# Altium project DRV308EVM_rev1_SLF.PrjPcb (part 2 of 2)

## Sheet DRV7308EVM_rev1_POWER_AND_CONNECTORS_SLF.SchDoc
size 431 x 279 mm; Date: Not shown in title block; ApprovedBy: Not shown in title block; CheckedBy: Not shown in title block; Author: Not shown in title block; CompanyName: Not shown in title block; DrawnBy: Anthony Lodi; Engineer: Not shown in title block; Organization: Not shown in title block; Address1: Not shown in title block; Address2: Not shown in title block; Address3: Not shown in title block; Address4: Not shown in title block; DocumentNumber: 2; Revision: Use project parameter SCH_Rev; SheetNumber: 2; SheetTotal: 3; PageSetup: Record=PageOptions¦CenterHorizontal=True¦CenterVertical=True¦PrintScale=1.00¦XCorrection=1.00¦YCorrection=1.00¦PrintKind=0¦BorderSize=5000000¦LeftOffset=0¦BottomOffset=0¦Orientation=2¦PaperLength=1000¦PaperWidth=1000¦Scale=100¦PaperSource=15¦PrintQuality=600¦MediaType=1¦DitherType=10¦PaperKind=Letter¦PrintScaleMode=1
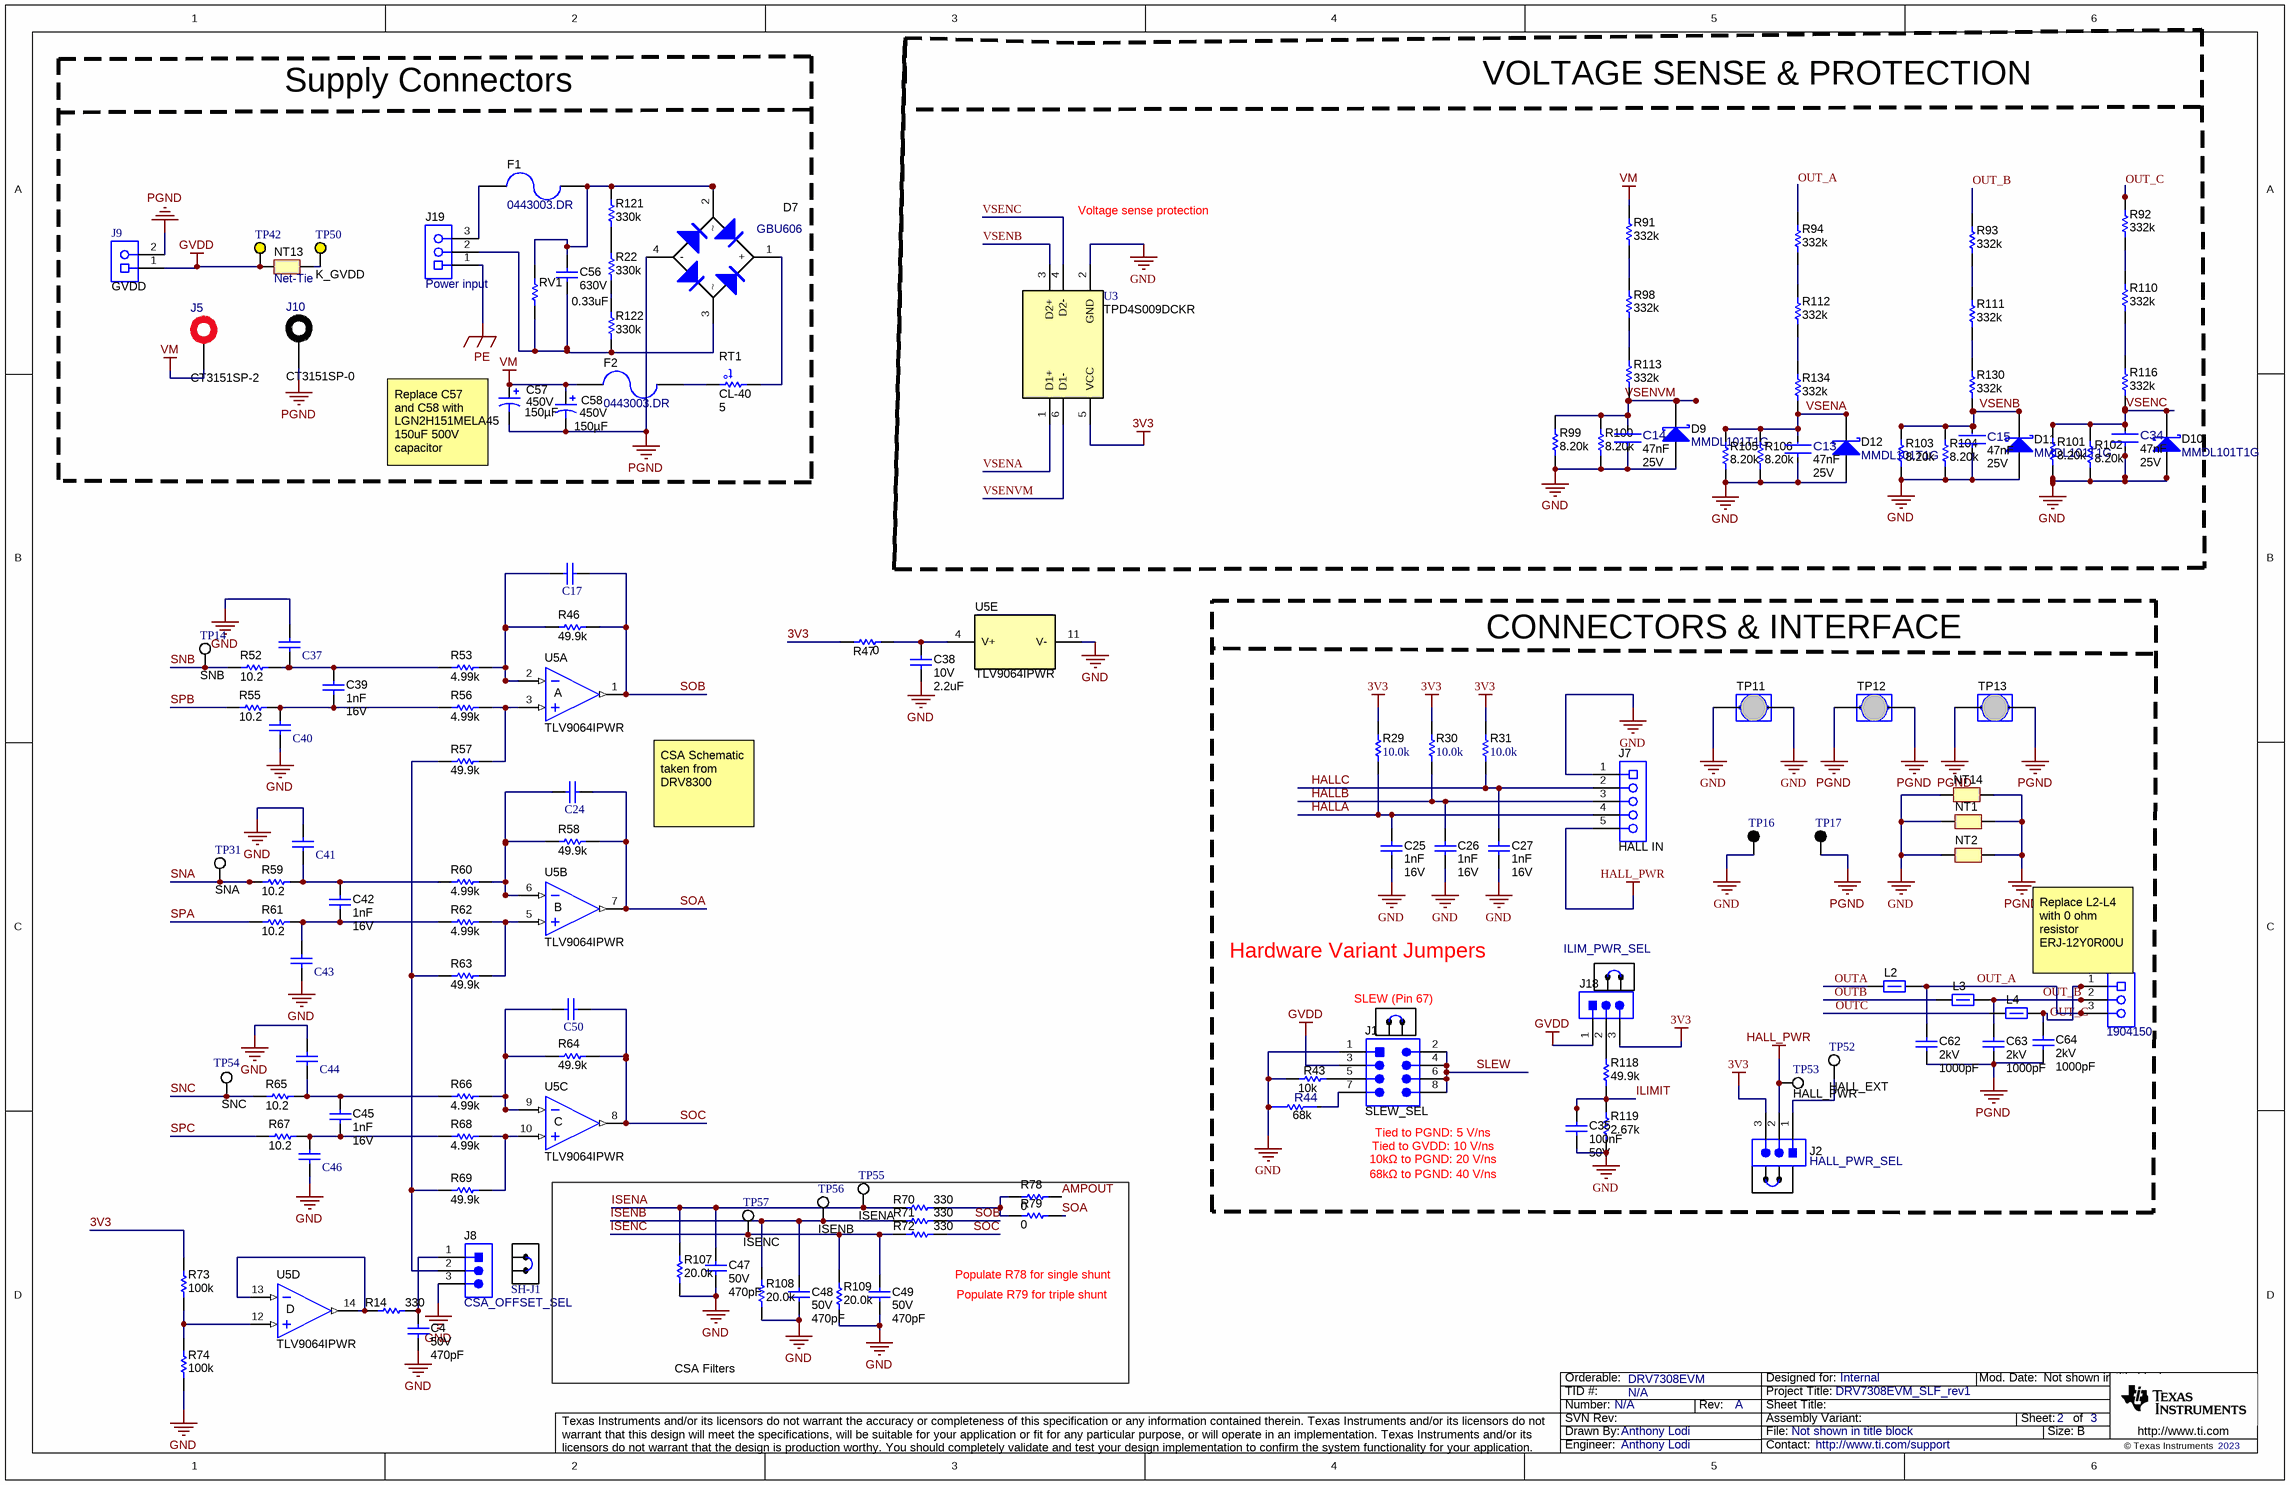
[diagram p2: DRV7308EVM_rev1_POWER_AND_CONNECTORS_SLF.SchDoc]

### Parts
C4  VDC_V: 50V  ValueDisplayed: 470pF  [0805L]  (hidden comment: C0805C471K5RACTU)
C13  Cap_F: 47nF  VDC_V: 25V  [FP-885012206069_0603-MFG]  (hidden comment: 885012206069)
C14  Cap_F: 47nF  VDC_V: 25V  [FP-885012206069_0603-MFG]  (hidden comment: 885012206069)
C15  Cap_F: 47nF  VDC_V: 25V  [FP-885012206069_0603-MFG]  (hidden comment: 885012206069)
C17  885012206003  [WCAP-CSGP_0603_L1.6W0.8H0.8_Reflow]  (value not drawn)
C24  885012206003  [WCAP-CSGP_0603_L1.6W0.8H0.8_Reflow]  (value not drawn)
C25  Cap_F: 1nF  VDC_V: 16V  [0603L]  (hidden comment: 885012206034)
C26  Cap_F: 1nF  VDC_V: 16V  [0603L]  (hidden comment: 885012206034)
C27  Cap_F: 1nF  VDC_V: 16V  [0603L]  (hidden comment: 885012206034)
C34  Cap_F: 47nF  VDC_V: 25V  [FP-885012206069_0603-MFG]  (hidden comment: 885012206069)
C35  Cap_F: 100nF  VDC_V: 50V  [0603L]  (hidden comment: 885012206095)
C37  885012206003  [WCAP-CSGP_0603_L1.6W0.8H0.8_Reflow]  (value not drawn)
C38  VDC_V: 10V  ValueDisplayed: 2.2uF  [0402L]  (hidden comment: C1005X5R1A225K050BC)
C39  Cap_F: 1nF  VDC_V: 16V  [0603L]  (hidden comment: 885012206034)
C40  885012206003  [WCAP-CSGP_0603_L1.6W0.8H0.8_Wave]  (value not drawn)
C41  885012206003  [WCAP-CSGP_0603_L1.6W0.8H0.8_Reflow]  (value not drawn)
C42  Cap_F: 1nF  VDC_V: 16V  [0603L]  (hidden comment: 885012206034)
C43  885012206003  [WCAP-CSGP_0603_L1.6W0.8H0.8_Reflow]  (value not drawn)
C44  885012206003  [WCAP-CSGP_0603_L1.6W0.8H0.8_Reflow]  (value not drawn)
C45  Cap_F: 1nF  VDC_V: 16V  [0603L]  (hidden comment: 885012206034)
C46  885012206003  [WCAP-CSGP_0603_L1.6W0.8H0.8_Reflow]  (value not drawn)
C47  VDC_V: 50V  ValueDisplayed: 470pF  [0805L]  (hidden comment: C0805C471K5RACTU)
C48  VDC_V: 50V  ValueDisplayed: 470pF  [0805L]  (hidden comment: C0805C471K5RACTU)
C49  VDC_V: 50V  ValueDisplayed: 470pF  [0805L]  (hidden comment: C0805C471K5RACTU)
C50  885012206003  [WCAP-CSGP_0603_L1.6W0.8H0.8_Reflow]  (value not drawn)
C56  VDC_V: 630V  ValueDisplayed: 0.33uF  [B32922_14.5mm]  (hidden comment: B32922C3334M)
C57  VDC_V: 450V  ValueDisplayed: 150µF  [381LQ_J02]  (hidden comment: 381LQ151M450J022)
C58  VDC_V: 450V  ValueDisplayed: 150µF  [381LQ_J02]  (hidden comment: 381LQ151M450J022)
C62  VDC_V: 2kV  ValueDisplayed: 1000pF  [1808]  (hidden comment: GR442QR73D102KW01L)
C63  VDC_V: 2kV  ValueDisplayed: 1000pF  [1808]  (hidden comment: GR442QR73D102KW01L)
C64  VDC_V: 2kV  ValueDisplayed: 1000pF  [1808]  (hidden comment: GR442QR73D102KW01L)
D7  GBU606  [GBU]
D9  MMDL101T1G  [SOD-323]
D10  MMDL101T1G  [SOD-323]
D11  MMDL101T1G  [SOD-323]
D12  MMDL101T1G  [SOD-323]
F1  0443003.DR  [FUSE_0443]
F2  0443003.DR  [FUSE_0443]
J1  SLEW_SEL  [TSW-104-07-G-D]
J2  HALL_PWR_SEL  [FCI_68001-403HLF]
J5  CT3151SP-2  [CTE_CT3151SP-2]
J6  1904150  [Phoenix_1904150]
J7  HALL IN  [Phoenix_1792892]
J8  CSA_OFFSET_SEL  [WURTH_61300311121]
J9  GVDD  [On-Shore_OSTVN02A150]
J10  CT3151SP-0  [CTE_CT3151SP-0]
J18  ILIM_PWR_SEL  [FCI_68001-403HLF]
J19  Power input  [Phoenix_1904150]
L2  742792511  [1812_170_HighSpeed]  (value not drawn)
L3  742792511  [1812_170_HighSpeed]  (value not drawn)
L4  742792511  [1812_170_HighSpeed]  (value not drawn)
NT1  Net-Tie  [Net-Tie_50milWide_30milLong]  (value not drawn)  (net tie, no BOM)
NT2  Net-Tie  [Net-Tie_50milWide_30milLong]  (value not drawn)  (net tie, no BOM)
NT13  Net-Tie  [Net-Tie_10milWide_30milLong]  (net tie, no BOM)
NT14  Net-Tie  [Net-Tie_50milWide_30milLong]  (value not drawn)  (net tie, no BOM)
R14  ValueDisplayed: 330  [0805L]  (hidden comment: CRCW0805330RFKEAC)
R22  ValueDisplayed: 330k  [1206]  (hidden comment: RC1206FR-07330KL)
R29  ValueDisplayed: 10.0k  [TNPW0603]  (hidden comment: TNPW060310K0BEEA)
R30  ValueDisplayed: 10.0k  [TNPW0603]  (hidden comment: TNPW060310K0BEEA)
R31  ValueDisplayed: 10.0k  [TNPW0603]  (hidden comment: TNPW060310K0BEEA)
R43  value 10k  [0603L]  (hidden comment: CRCW060310K0JNEA)
R44  Res_ohm: 68k  [FP-CRCW060368K0FKEA_0603-MFG]  (hidden comment: CRCW060368K0FKEA)
R46  ValueDisplayed: 49.9k  [0603L]  (hidden comment: CRCW060349K9FKEA)
R47  value 0  [0603L]  (hidden comment: CRCW06030000Z0EA)
R52  ValueDisplayed: 10.2  [0603L]  (hidden comment: CRCW060310R2FKEA)
R53  ValueDisplayed: 4.99k  [0603L]  (hidden comment: CRCW06034K99FKEA)
R55  ValueDisplayed: 10.2  [0603L]  (hidden comment: CRCW060310R2FKEA)
R56  ValueDisplayed: 4.99k  [0603L]  (hidden comment: CRCW06034K99FKEA)
R57  ValueDisplayed: 49.9k  [0603L]  (hidden comment: CRCW060349K9FKEA)
R58  ValueDisplayed: 49.9k  [0603L]  (hidden comment: CRCW060349K9FKEA)
R59  ValueDisplayed: 10.2  [0603L]  (hidden comment: CRCW060310R2FKEA)
R60  ValueDisplayed: 4.99k  [0603L]  (hidden comment: CRCW06034K99FKEA)
R61  ValueDisplayed: 10.2  [0603L]  (hidden comment: CRCW060310R2FKEA)
R62  ValueDisplayed: 4.99k  [0603L]  (hidden comment: CRCW06034K99FKEA)
R63  ValueDisplayed: 49.9k  [0603L]  (hidden comment: CRCW060349K9FKEA)
R64  ValueDisplayed: 49.9k  [0603L]  (hidden comment: CRCW060349K9FKEA)
R65  ValueDisplayed: 10.2  [0603L]  (hidden comment: CRCW060310R2FKEA)
R66  ValueDisplayed: 4.99k  [0603L]  (hidden comment: CRCW06034K99FKEA)
R67  ValueDisplayed: 10.2  [0603L]  (hidden comment: CRCW060310R2FKEA)
R68  ValueDisplayed: 4.99k  [0603L]  (hidden comment: CRCW06034K99FKEA)
R69  ValueDisplayed: 49.9k  [0603L]  (hidden comment: CRCW060349K9FKEA)
R70  ValueDisplayed: 330  [0805L]  (hidden comment: CRCW0805330RFKEAC)
R71  ValueDisplayed: 330  [0805L]  (hidden comment: CRCW0805330RFKEAC)
R72  ValueDisplayed: 330  [0805L]  (hidden comment: CRCW0805330RFKEAC)
R73  ValueDisplayed: 100k  [0603L]  (hidden comment: CRCW0603100KFKEA)
R74  ValueDisplayed: 100k  [0603L]  (hidden comment: CRCW0603100KFKEA)
R78  ValueDisplayed: 0  [0603L]  (hidden comment: ERJ-3GEY0R00V)
R79  ValueDisplayed: 0  [0603L]  (hidden comment: ERJ-3GEY0R00V)
R91  ValueDisplayed: 332k  [1206]  (hidden comment: RC1206FR-07332KL)
R92  ValueDisplayed: 332k  [1206]  (hidden comment: RC1206FR-07332KL)
R93  ValueDisplayed: 332k  [1206]  (hidden comment: RC1206FR-07332KL)
R94  ValueDisplayed: 332k  [1206]  (hidden comment: RC1206FR-07332KL)
R98  ValueDisplayed: 332k  [1206]  (hidden comment: RC1206FR-07332KL)
R99  ValueDisplayed: 8.20k  [0603]  (hidden comment: RC0603FR-078K2L)
R100  ValueDisplayed: 8.20k  [0603]  (hidden comment: RC0603FR-078K2L)
R101  ValueDisplayed: 8.20k  [0603]  (hidden comment: RC0603FR-078K2L)
R102  ValueDisplayed: 8.20k  [0603]  (hidden comment: RC0603FR-078K2L)
R103  ValueDisplayed: 8.20k  [0603]  (hidden comment: RC0603FR-078K2L)
R104  ValueDisplayed: 8.20k  [0603]  (hidden comment: RC0603FR-078K2L)
R105  ValueDisplayed: 8.20k  [0603]  (hidden comment: RC0603FR-078K2L)
R106  ValueDisplayed: 8.20k  [0603]  (hidden comment: RC0603FR-078K2L)
R107  ValueDisplayed: 20.0k  [0805L]  (hidden comment: CRCW080520K0FKEA)
R108  ValueDisplayed: 20.0k  [0805L]  (hidden comment: CRCW080520K0FKEA)
R109  ValueDisplayed: 20.0k  [0805L]  (hidden comment: CRCW080520K0FKEA)
R110  ValueDisplayed: 332k  [1206]  (hidden comment: RC1206FR-07332KL)
R111  ValueDisplayed: 332k  [1206]  (hidden comment: RC1206FR-07332KL)
R112  ValueDisplayed: 332k  [1206]  (hidden comment: RC1206FR-07332KL)
R113  ValueDisplayed: 332k  [1206]  (hidden comment: RC1206FR-07332KL)
R116  ValueDisplayed: 332k  [1206]  (hidden comment: RC1206FR-07332KL)
R118  ValueDisplayed: 49.9k  [0603L]  (hidden comment: CRCW060349K9FKEA)
R119  ValueDisplayed: 2.67k  [0603L]  (hidden comment: CRCW06032K67FKEA)
R121  ValueDisplayed: 330k  [1206]  (hidden comment: RC1206FR-07330KL)
R122  ValueDisplayed: 330k  [1206]  (hidden comment: RC1206FR-07330KL)
R130  ValueDisplayed: 332k  [1206]  (hidden comment: RC1206FR-07332KL)
R134  ValueDisplayed: 332k  [1206]  (hidden comment: RC1206FR-07332KL)
RT1  CL-40  value 5  [Thermistor_CL-40]
RV1  B72210P2351K101  [FP-B72210P2351K101_RADIAL-MFG]  (value not drawn)
SH-J1  SNT-100-BK-G  [SNT-100-BK-G]  (value not drawn)
SH-J3  SNT-100-BK-G  [SNT-100-BK-G]  (value not drawn)
SH-J4  SNT-100-BK-G  [SNT-100-BK-G]  (value not drawn)
SH-J5  SNT-100-BK-G  [SNT-100-BK-G]  (value not drawn)
TP11  GND  [Harwin_D3082-05]  (value not drawn)
TP12  PGND  [Harwin_D3082-05]  (value not drawn)
TP13  PGND  [Harwin_D3082-05]  (value not drawn)
TP14  SNB  [Keystone5002]
TP16  GND  [Keystone5001]  (value not drawn)
TP17  PGND  [Keystone5001]  (value not drawn)
TP31  SNA  [Keystone5002]
TP42  GVDD  [Keystone5009]  (value not drawn)
TP50  K_GVDD  [Keystone5009]
TP52  HALL_EXT  [Keystone5002]
TP53  HALL_PWR  [Keystone5002]
TP54  SNC  [Keystone5002]
TP55  ISENA  [Keystone5002]
TP56  ISENB  [Keystone5002]
TP57  ISENC  [Keystone5002]
U3  TPD4S009DCKR  [DCK0006A_N]
U5  TLV9064IPWR  [PW0014A_N]  (parts A,B,C,D,E of 5)

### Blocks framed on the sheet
CONNECTORS & INTERFACE: C25-C27 C35 C62-C64 J1 J2 J6 J7 J18 L2-L4 NT1 NT2 NT14 R29-R31 R43 R44 R118 R119 SH-J3-SH-J5 TP11-TP13 TP16 TP17 TP52 TP53

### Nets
3V3: J2.3 J18.3 R29.2 R30.2 R31.2 R47.2 R73.2 U3.5(VCC)
GND: C4.2 C13.1 C14.1 C15.1 C25.2 C26.2 C27.2 C34.1 C35.2 C37.1 C38.1 C40.2 C41.1 C43.2 C44.1 C46.2 C47.2 C48.2 C49.2 D9.2(A) D10.2(A) D11.2(A) D12.2(A) J1.1 J7.1 J8.3 NT1.1 NT2.1 NT14.1 R43.1 R44.1 R74.1 R99.1 R100.1 R101.1 R102.1 R103.1 R104.1 R105.1 R106.1 R107.1 R108.1 R109.1 R119.1 TP11.1 TP11.2 TP16.1 U3.2(GND) U5.11(V-)
GVDD: J1.3 J9.1 J18.1 NT13.2 TP42.1
HALL_PWR: J2.2 J7.5 TP53.1
PE: J19.1
PGND: C57.2(-) C58.2(-) C62.2 C63.2 C64.2 D7.4(-) J9.2 J10.1 NT1.2 NT2.2 NT14.2 TP12.1 TP12.2 TP13.1 TP13.2 TP17.1
VM: C57.1(+) C58.1(+) F2.2 J5.1 R91.2
AMPOUT: R78.2
HALLA: C25.1 J7.4 R29.1
HALLB: C26.1 J7.3 R30.1
HALLC: C27.1 J7.2 R31.1
ILIMIT: C35.1 R118.1 R119.2
ISENA: C47.1 R70.1 R107.2 TP55.1
ISENB: C48.1 R71.1 R108.2 TP56.1
ISENC: C49.1 R72.1 R109.2 TP57.1
OUT_A: C62.1 J6.3 L2.2 R94.2
OUT_B: C63.1 J6.2 L3.2 R93.2
OUT_C: C64.1 J6.1 L4.2 R92.2
OUTA: L2.1
OUTB: L3.1
OUTC: L4.1
SLEW: J1.2 J1.4 J1.6 J1.8
SNA: R59.1 TP31.1
SNB: R52.1 TP14.1
SNC: R65.1 TP54.1
SOA: C24.2 R58.2 R79.2 U5.7(OUT)
SOB: C17.2 R46.2 R71.2 U5.1(OUT)
SOC: C50.2 R64.2 R72.2 U5.8(OUT)
SPA: R61.1
SPB: R55.1
SPC: R67.1
VSENA: C13.2 D12.1(K) R105.2 R106.2 R134.1 U3.1(D1+)
VSENB: C15.2 D11.1(K) R103.2 R104.2 R130.1 U3.3(D2+)
VSENC: C34.2 D10.1(K) R101.2 R102.2 R116.1 U3.4(D2-)
VSENVM: C14.2 D9.1(K) R99.2 R100.2 R113.1 U3.6(D1-)
NetC4_1: C4.1 J8.1 R14.2
NetC17_1: C17.1 R46.1 R53.2 U5.2(IN-)
NetC24_1: C24.1 R58.1 R60.2 U5.6(IN-)
NetC37_2: C37.2 C39.1 R52.2 R53.1
NetC38_2: C38.2 R47.1 U5.4(V+)
NetC39_2: C39.2 C40.1 R55.2 R56.1
NetC41_2: C41.2 C42.1 R59.2 R60.1
NetC42_2: C42.2 C43.1 R61.2 R62.1
NetC44_2: C44.2 C45.1 R65.2 R66.1
NetC45_2: C45.2 C46.1 R67.2 R68.1
NetC50_1: C50.1 R64.1 R66.2 U5.9(IN-)
NetC56_1: C56.1 D7.2 F1.1 R121.2 RV1.2
NetC56_2: C56.2 D7.3 J19.2 R122.1 RV1.1
NetD7_1: D7.1(+) RT1.1
NetF1_2: F1.2 J19.3
NetF2_1: F2.1 RT1.2
NetJ1_5: J1.5 R43.2
NetJ1_7: J1.7 R44.2
NetJ2_1: J2.1 TP52.1
NetJ8_2: J8.2 R57.2 R63.2 R69.2
NetJ18_2: J18.2 R118.2
NetNT13_1: NT13.1 TP50.1
NetR14_1: R14.1 U5.13(IN-) U5.14(OUT)
NetR22_1: R22.1 R122.2
NetR22_2: R22.2 R121.1
NetR56_2: R56.2 R57.1 U5.3(IN+)
NetR62_2: R62.2 R63.1 U5.5(IN+)
NetR68_2: R68.2 R69.1 U5.10(IN+)
NetR70_2: R70.2 R78.1 R79.1
NetR73_1: R73.1 R74.2 U5.12(IN+)
NetR91_1: R91.1 R98.2
NetR92_1: R92.1 R110.2
NetR93_1: R93.1 R111.2
NetR94_1: R94.1 R112.2
NetR98_1: R98.1 R113.2
NetR110_1: R110.1 R116.2
NetR111_1: R111.1 R130.2
NetR112_1: R112.1 R134.2

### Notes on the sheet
- Supply Connectors
- VOLTAGE SENSE & PROTECTION
- Voltage sense protection
- (near C57) Replace C57 and C58 with LGN2H151MELA45 150uF 500V capacitor
- CSA Schematic taken from DRV8300
- Hardware Variant Jumpers
- (near J6) Replace L2-L4 with 0 ohm resistor ERJ-12Y0R00U
- (near SH-J4) SLEW (Pin 67)
- (near J1) Tied to PGND: 5 V/ns
- Tied to GVDD: 10 V/ns
- 10kΩ to PGND: 20 V/ns
- 68kΩ to PGND: 40 V/ns
- Populate R79 for triple shunt
- Populate R78 for single shunt
- CSA Filters

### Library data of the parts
C4 C47-C49 = CMP-0007796-2: CAP, CERM, 470 pF, 50 V, +/- 10%, X7R, 0805; Manufacturer: Kemet; TaMin_C: -55°C; ESR_ohm: 0.688; Polarized: N; SizeAreaWB_mm2: 6.75; Value1: 0.688 ohm; U/M: EA; Value: 470pF; TaMax_C: 125°C; SizeZ_mm: 1.45; SizeX_mm: 2; SizeY_mm: 1.25; Cap_Case: 0805; SizeArea_mm2: 2.5; IRMS_A: 213mA; AEC Category: Q200
C13-C15 C34 = CMP-0086483-1: 0.047µF ±10% 25V Ceramic Capacitor X7R 0603 (1608 Metric); Manufacturer: Wurth Electronics; SizeZ_mm: 0.95mm; TempCo: 15%; Symbol Name: SYM-885012206069; AEC Qualified: No
C17 C24 C37 C40 C41 C43 C44 C46 C50 = CMP-0104643-1: WCAP-CSGP Multilayer Ceramic Chip Capacitor, General Purpose, size 0603, X7R, 100pF, 10VDC; Manufacturer: Wurth Elektronik; Capacitance Tolerance: +/-10%; Case/Size Code: 0603; Dissipation Factor: 5%; Insulation Resistance: 10GOhm; Rated Voltage (DC): 10V; Technical Reference: X7R0603101K010DFCT10000
C25-C27 = CMP-0006826-2: CAP, CERM, 1000 pF, 16 V, +/- 10%, X7R, 0603; Manufacturer: Wurth Elektronik; TaMin_C: -55°C; Polarized: N; SizeAreaWB_mm2: 4.68; Value1: Unknown; U/M: EA; Value: 1000pF; TaMax_C: 125°C; SizeZ_mm: 1; SizeX_mm: 1.6; SizeY_mm: 0.8; Cap_Case: 0603; SizeArea_mm2: 1.28; AEC Category: Q200
C35 = CMP-0006837-2: CAP, CERM, 0.1 uF, 50 V, +/- 10%, X7R, 0603; Manufacturer: Wurth Elektronik; TaMin_C: -55°C; Polarized: N; SizeAreaWB_mm2: 4.68; Value1: Unknown; U/M: EA; Value: 0.1uF; TaMax_C: 125°C; SizeZ_mm: 1; SizeX_mm: 1.6; SizeY_mm: 0.8; Cap_Case: 0603; SizeArea_mm2: 1.28; AEC Category: Q200
C38 = CMP-0006263-2: CAP, CERM, 2.2 uF, 10 V, +/- 10%, X5R, 0402; Manufacturer: TDK; TaMin_C: -55°C; Polarized: N; SizeAreaWB_mm2: 3; Value1: Unknown; U/M: EA; Value: 2.2uF; TaMax_C: 85°C; SizeZ_mm: 0.6; SizeX_mm: 1; SizeY_mm: 0.5; Cap_Case: 0402; Cap_F: 2.2µF; AEC Category: Q200
C39 C42 C45 = CMP-0006826-4: CAP, CERM, 1000 pF, 16 V, +/- 10%, X7R, 0603; Manufacturer: Wurth Elektronik; TaMin_C: -55°C; Polarized: N; SizeAreaWB_mm2: 4.68; Value1: Unknown; U/M: EA; Value: 1000pF; TaMax_C: 125°C; SizeZ_mm: 1; SizeX_mm: 1.6; SizeY_mm: 0.8; Cap_Case: 0603; SizeArea_mm2: 1.28; AEC Category: Q200
C56 = CMP-0012410-1: CAP, Film, 0.33 uF, 630 V, +/- 20%, TH; Manufacturer: TDK; Polarized: N; SizeAreaWB_mm2: 210; Value1: Unknown; U/M: EA; Value: 0.33uF; TaMax_C: 110°C; SizeZ_mm: 14.5; SizeX_mm: 18; SizeY_mm: 8.5; SizeArea_mm2: 153; Cap_F: 330nF; AEC Category: Q200
C57 C58 = CMP-0085509-1: CAP, AL, 150 µF, 450 V, +/- 20%, 1.216 ohm, TH; Manufacturer: Cornell Dubilier Electronics; SizeZ_mm: 32; SizeX_mm: 25; ESR_ohm: 1.216; IRMS_A: 790mA; U/M: EA; Value: 150uF; AEC Qualified: N; SizeAreaWB_mm2: 729; CompType: Capacitor; Polarized: Y; AEC Category: Q200; TaMax_C: 105°C; Cap_Case: 25x30mm; SizeArea_mm2: 625; TaMin_C: -55°C
C62-C64 = CMP-0009436-1: CAP, CERM, 1000 pF, 2000 V, +/- 10%, X7R, 1808; Manufacturer: MuRata; TaMin_C: -55°C; Polarized: N; SizeAreaWB_mm2: 16.5; Value1: Unknown; U/M: EA; Value: 1000pF; TaMax_C: 125°C; SizeZ_mm: 2.03; SizeX_mm: 4.5; SizeY_mm: 2; Value2: 2000V; SizeArea_mm2: 9; Cap_F: 1nF; AEC Category: Q200
D7 = CMP-0029245-3: Diode, Switching-Bridge, 600 V, 6 A, TH; Manufacturer: Diodes Inc.; SizeZ_mm: 21.55; SizeAreaWB_mm2: 130.5915; RJC_CperW: 2.2; SizeX_mm: 22.05; Value: 600V; TJmax_C: 150°C; Green_Lifecycle: Not Set; Io_A: 6A; Value2: 1V; SizeY_mm: 3.43; Green_REACh: Incomplete; AEC Category: Q101; SizeArea_mm2: 75.6315; AEC Qualified: N
D9-D12 = CMP-0084035-2: Diode, Schottky, 7 V, 0.01 A, SOD-323; Manufacturer: ON Semiconductor; SizeY_mm: 1.35; SizeX_mm: 2.7; SizeAreaWB_mm2: 8.695; AEC Qualified: N; SizeArea_mm2: 3.645; Value1: 0.01A; Value2: 0.6V; SizeZ_mm: 1; Io_A: 10mA; Vr_V: 7V; AEC Category: Q101; Value: 7V; Vf_V: 600mV; TJmax_C: 150°C
F1 F2 = CMP-0003468-2: Fuse, 3 A, 250VAC/VDC, SMD; Manufacturer: Littelfuse; Irating_A: 3A; Interrupt_AC: 50A; VAC_V: 250V; Rtyp_Ohm: 0.028; MeltingTyp: 51.44
J1 = CMP-0075408-2: Header, 100mil, 4x2, Gold, TH; Manufacturer: Samtec; Pitch_mm: 2.54; Cert_VDE: N; Gender: Male; Cert_CSA: Y; Voltage_V: 550V; Green_REACh: Passed; Current_A: 6.3A; Green_Lifecycle: Active; Row_Count: 2
J2 J18 = CMP-0065026-1: Header, 2.54mm, 3x1, Tin, TH; Manufacturer: FCI; PartNumber: 68001-403HLF; CNHeader: True; Current_A: 3A; Shrouded: N; Gender: Male; Cert_CSA: Y; Voltage_V: 1.5kV; Row_Count: 1; Pitch_mm: 2.54; CT: False
J5 = CMP-0055418-2: Banana Jack Insul Nylon Red, R/A, TH; Manufacturer: Cal Test Electronics; CNHeader: FALSE; Current_A: 25A; Gender: Female; Voltage_V: 1kV; Row_Count: 1; ContactFinish: Nickel; CT: TRUE; Cert_UL: Y
J6 = CMP-0055528-1: Terminal Block, 9.52mm, 3x1, R/A, TH; Manufacturer: Phoenix Contact; Cert_VDE: Y; CNHeader: FALSE; Current_A: 32A; Gender: Female; Voltage_V: 1kV; Row_Count: 1; Pitch_mm: 9.52; CT: TRUE
J7 = CMP-0055532-1: Terminal Block, 5mm, 5x1, R/A, TH; Manufacturer: Phoenix Contact; PartNumber: 1792892; Cert_VDE: Y; CNHeader: FALSE; Current_A: 16A; Gender: Female; Voltage_V: 400V; Row_Count: 1; Pitch_mm: 5; CT: TRUE
J8 = CMP-0054796-2: Header, 2.54 mm, 3x1, Gold, TH; Manufacturer: Wurth Elektronik; PartNumber: 61300311121; Green_Lifecycle: Active; Green_REACh: Passed; Cert_UL: Y; Gender: Male; Pitch_mm: 2.54; Row_Count: 1; Shrouded: N
J9 = CMP-0075076-1: Terminal Block, 2.54mm, 2x1, Brass, TH; Manufacturer: On-Shore Technology; PartNumber: OSTVN02A150; CT: True; Green_REACh: Incomplete; CNHeader: False; Green_Lifecycle: Not Set
J10 = CMP-0055417-2: Banana Jack Insul Nylon Black, R/A, TH; Manufacturer: Cal Test Electronics; CNHeader: FALSE; Current_A: 25A; Gender: Female; Voltage_V: 1kV; Row_Count: 1; ContactFinish: Nickel; CT: TRUE; Cert_UL: Y
J19 = CMP-0055528-1: Terminal Block, 9.52mm, 3x1, R/A, TH; Manufacturer: Phoenix Contact; PartNumber: 1904150; Cert_VDE: Y; CNHeader: FALSE; Current_A: 32A; Gender: Female; Voltage_V: 1kV; Row_Count: 1; Pitch_mm: 9.52; CT: TRUE
L2-L4 = CMP-0003168-1: Ferrite Bead, 120 ohm @ 100 MHz, 3 A, 1812; Manufacturer: Wurth Elektronik; Ztyp@1GHz_Ohm: 162.455; ZTyp@100MHz_Ohm: 120; SizeAreaWB_mm2: 23.1; DCR_ohm: 0.05; Value1: 0.05 ohm; Value: 120 ohm; Imax_A: 3A; SizeZ_mm: 1.7; SizeX_mm: 4.5; SizeY_mm: 3.2; SizeArea_mm2: 14.4
NT1 NT2 NT14 = CMP-0078142-1: Single point connection between nets.
NT13 = CMP-0078142-4: Single point connection between nets.
R14 R70-R72 = CMP-0082535-1: RES, 330, 1%, 0.125 W, 0805; Manufacturer: Vishay-Dale; Power_W: 125mW; TempCo: 100 ppm/C; SizeAreaWB_mm2: 6.75; Value_Code: 330R; Value: 330; SizeX_mm: 2; SizeY_mm: 1.25; SizeZ_mm: 1.45; Value2: 0.125W; SizeArea_mm2: 2.5; AEC Qualified: N; VDC_V: 150V; AEC Category: Q200
R22 R121 R122 = CMP-0018205-2: RES, 330 k, 1%, 0.25 W, 1206; Manufacturer: Yageo America; Power_W: 250mW; TempCo: 100 ppm/C; U/M: EA; Value: 330k; SizeX_mm: 3.2; SizeY_mm: 1.6; SizeZ_mm: 1.35; Value2: 0.25W; SizeArea_mm2: 5.12; VDC_V: 200V; AEC Category: Q200
R29-R31 = CMP-0025686-1: RES, 10.0 k, 0.1%, 0.1 W, AEC-Q200 Grade 1, 0603; Manufacturer: Vishay-Dale; Power_W: 100mW; TempCo: 25 ppm/C; Value_Code: 10k0; U/M: EA; Value: 10.0k; EIA_Code: E192; Res_ohm: 10k; SizeX_mm: 1.6; SizeY_mm: 0.85; SizeZ_mm: 0.55; Value2: 0.1W; SizeArea_mm2: 1.36; AEC Qualified: Y; VDC_V: 75V; AEC Grade: 1; AEC Category: Q200
R43 = CMP-0025701-4: RES, 10 k, 5%, 0.1 W, AEC-Q200 Grade 0, 0603; Manufacturer: Vishay-Dale; Value_Code: 10k0; Power_W: 100mW; Value2: 0.1W; VDC_V: 75V; TempCo: 200 ppm/C; EIA_Code: E24; AEC Category: Q200; AEC Qualified: Y; AEC Grade: 0; SizeArea_mm2: 1.28; SizeX_mm: 1.6; SizeY_mm: 0.8; SizeZ_mm: 1
R44 = CMP-0095619-1: RES Thick Film, 68kΩ, 1%, 0.1W, 100ppm/°C, 0603; Manufacturer: Vishay; Approved Alternate Part Number: 541-1.00HHCT-ND; SizeZ_mm: 0.5mm; Power_W: 100mW; AEC Grade: Grade 0; AEC Qualified: Yes; Voltage: 75V; Value: 68k
R46 R57 R58 R63 R64 R69 R118 = CMP-0022447-4: RES, 49.9 k, 1%, 0.1 W, AEC-Q200 Grade 0, 0603; Manufacturer: Vishay-Dale; Power_W: 100mW; TempCo: 100 ppm/C; Value_Code: 49k9; Value: 49.9k; EIA_Code: E96; SizeX_mm: 1.6; SizeY_mm: 0.8; SizeZ_mm: 1; Value2: 0.1W; SizeArea_mm2: 1.28; AEC Qualified: Y; VDC_V: 75V; AEC Category: Q200; AEC Grade: 0
R47 = CMP-0025697-4: RES, 0, 5%, 0.1 W, AEC-Q200 Grade 0, 0603; Manufacturer: Vishay-Dale; Value_Code: 0000; Power_W: 100mW; Value2: 0.1W; VDC_V: 75V; TempCo: 200 ppm/C; EIA_Code: E24; AEC Category: Q200; AEC Qualified: Y; SizeArea_mm2: 1.28; SizeX_mm: 1.6; SizeY_mm: 0.8; SizeZ_mm: 1
R52 R55 R59 R61 R65 R67 = CMP-0022005-4: RES, 10.2, 1%, 0.1 W, AEC-Q200 Grade 0, 0603; Manufacturer: Vishay-Dale; Power_W: 100mW; TempCo: 100 ppm/C; Value_Code: 10R2; Value: 10.2; EIA_Code: E96; SizeX_mm: 1.6; SizeY_mm: 0.8; SizeZ_mm: 1; Value2: 0.1W; SizeArea_mm2: 1.28; AEC Qualified: Y; VDC_V: 75V; AEC Category: Q200; AEC Grade: 0
R53 R56 R60 R62 R66 R68 = CMP-0022458-4: RES, 4.99 k, 1%, 0.1 W, AEC-Q200 Grade 0, 0603; Manufacturer: Vishay-Dale; Power_W: 100mW; TempCo: 100 ppm/C; Value_Code: 4k99; Value: 4.99k; EIA_Code: E96; SizeX_mm: 1.6; SizeY_mm: 0.8; SizeZ_mm: 1; Value2: 0.1W; SizeArea_mm2: 1.28; AEC Qualified: Y; VDC_V: 75V; AEC Category: Q200; AEC Grade: 0
R73 R74 = CMP-0021990-4: RES, 100 k, 1%, 0.1 W, AEC-Q200 Grade 0, 0603; Manufacturer: Vishay-Dale; Power_W: 100mW; TempCo: 100 ppm/C; Value: 100k; EIA_Code: E96; SizeX_mm: 1.6; SizeY_mm: 0.8; SizeZ_mm: 1; Value2: 0.1W; SizeArea_mm2: 1.28; AEC Qualified: Y; VDC_V: 75V; AEC Category: Q200; AEC Grade: 0
R78 R79 = CMP-0025874-4: RES, 0, 5%, 0.1 W, AEC-Q200 Grade 0, 0603; Manufacturer: Panasonic; Power_W: 100mW; TempCo: 600 ppm/C; Value_Code: 0000; Value: 0; EIA_Code: E24; SizeX_mm: 1.6; SizeY_mm: 0.8; SizeZ_mm: 1; Value2: 0.1W; SizeArea_mm2: 1.28; AEC Qualified: Y; VDC_V: 50V; AEC Category: Q200; SizeAreaWB_mm2: 4.68
R91-R94 R98 R110-R113 R116 R130 R134 = CMP-0018207-2: RES, 332 k, 1%, 0.25 W, 1206; Manufacturer: Yageo America; Power_W: 250mW; TempCo: 100 ppm/C; U/M: EA; Value: 332k; EIA_Code: E96; SizeX_mm: 3.2; SizeY_mm: 1.6; SizeZ_mm: 1.35; Value2: 0.25W; SizeArea_mm2: 5.12; VDC_V: 200V; AEC Category: Q200
R99-R106 = CMP-0023308-5: RES, 8.20 k, 1%, 0.1 W, 0603; Manufacturer: Yageo; Power_W: 100mW; TempCo: 100 ppm/C; Value_Code: 8k20; Value: 8.20k; Res_ohm: 8.2k; SizeX_mm: 1.6; SizeY_mm: 0.8; SizeZ_mm: 1; Value2: 0.1W; SizeArea_mm2: 1.28; AEC Qualified: N; VDC_V: 75V; AEC Category: Q200; SizeAreaWB_mm2: 4.68
R107-R109 = CMP-0021042-1: RES, 20.0 k, 1%, 0.125 W, 0805; Manufacturer: Vishay-Dale; Power_W: 125mW; TempCo: 100 ppm/C; Value_Code: 20k0; U/M: EA; Value: 20.0k; EIA_Code: E96; Res_ohm: 20k; SizeX_mm: 2; SizeY_mm: 1.25; SizeZ_mm: 1.45; Value2: 0.125W; SizeArea_mm2: 2.5; VDC_V: 150V; AEC Category: Q200
R119 = CMP-0022280-2: RES, 2.67 k, 1%, 0.1 W, 0603; Manufacturer: Vishay-Dale; Power_W: 100mW; TempCo: 100 ppm/C; Value_Code: 2k67; U/M: EA; Value: 2.67k; EIA_Code: E96; SizeX_mm: 1.6; SizeY_mm: 0.8; SizeZ_mm: 1; Value2: 0.1W; SizeArea_mm2: 1.28; VDC_V: 75V; AEC Category: Q200
RT1 = CMP-0002561-2: Thermistor NTC, 5 ohm, 25%, Disc, 220x770 mil; Manufacturer: GE Sensing; TaMax_C: 175°C; SizeX_mm: 19.56; SizeY_mm: 5.59; TaMin_C: -50°C; Power_W: 180W; SizeArea_mm2: 109.3404; SizeAreaWB_mm2: 163.6404; U/M: EA
RV1 = CMP-0086467-2: Var MOV 350VAC/460VDC 3500A 560V Radial Bulk; Manufacturer: TDK; SizeZ_mm: 16.5mm
SH-J1 SH-J3-SH-J5 = CMP-0003623-3: Shunt, 100mil, Gold plated, Black; Alternate PartNumber: 969102-0000-DA; Manufacturer: Samtec; Alternate Manufacturer: 3M; Value: 1x2
TP11-TP13 = CMP-0075110-1: 1mm Uninsulated Shorting Plug, 10.16mm spacing, TH; Manufacturer: Harwin; PartNumber: D3082-05; CNHeader: False; Green_Lifecycle: Active; Green_REACh: Passed; CompType: Jumper Wire
TP14 TP31 TP52-TP57 = CMP-0055139-2: Test Point, Miniature, White, TH; Manufacturer: Keystone Electronics; ContactFinish: Silver; Green_REACh: Passed; CT: TRUE; Green_Lifecycle: Active; CNHeader: FALSE
TP16 TP17 = CMP-0055138-1: Test Point, Miniature, Black, TH; Manufacturer: Keystone; CNHeader: FALSE; Green_Lifecycle: Active; Green_REACh: Passed; ContactFinish: Silver; CT: TRUE
TP42 TP50 = CMP-0055146-2: Test Point, Compact, Yellow, TH; Manufacturer: Keystone Electronics; Green_REACh: Passed; ContactFinish: Silver; CT: TRUE; CNHeader: FALSE; Green_Lifecycle: Active
U3 = CMP-0043118-3: 4-Channel ESD Solution for High-Speed Differential Interface, DCK0006A (SOT-SC70-6); Manufacturer: Texas Instruments; IO Leakage Current(nA): 10; IO Capacitance(Typ)(pF): 0.8; Eco-Plan: Green (RoHS & no Sb/Br); Breakdown Voltage(Min)(V): 9; Differential Capacitance(pF): 0.05; AEC Category: Q200; AEC Qualified: N; CompType: IC; Rating: Catalog; SizeAreaWB_mm2: 9.3; SizeArea_mm2: 4.2; SizeX_mm: 2.1; SizeY_mm: 2.0; SizeZ_mm: 1.1
U5 = CMP-0082283-1: 4 channel, 10-MHz, Low-Noise, RRIO, CMOS Operational Amplifier for Cost-Sensitive Systems, PW0014A (TSSOP-14); Alternate PartNumber: TLV9064IPWT; Alternate Manufacturer: Texas Instruments; SizeAreaWB_mm2: 58.8; Rating: Catalog; SizeZ_mm: 1.2; SizeX_mm: 6.4; SizeY_mm: 5; SizeArea_mm2: 32; CompType: IC; AEC Qualified: N; AEC Category: Q200

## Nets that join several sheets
3V3: DRV7308EVM_rev1_DRIVER_SLF (10 pins), DRV7308EVM_rev1_POWER_AND_CONNECTORS_SLF (8 pins)
GND: DRV7308EVM_rev1_DRIVER_SLF (27 pins), DRV7308EVM_rev1_POWER_AND_CONNECTORS_SLF (49 pins)
GVDD: DRV7308EVM_rev1_DRIVER_SLF (9 pins), DRV7308EVM_rev1_POWER_AND_CONNECTORS_SLF (5 pins)
PGND: DRV7308EVM_rev1_DRIVER_SLF (23 pins), DRV7308EVM_rev1_POWER_AND_CONNECTORS_SLF (16 pins)
VM: DRV7308EVM_rev1_DRIVER_SLF (8 pins), DRV7308EVM_rev1_POWER_AND_CONNECTORS_SLF (5 pins)
AMPOUT: DRV7308EVM_rev1_DRIVER_SLF (C16.2 R128.2 TP39.1 U1.4), DRV7308EVM_rev1_POWER_AND_CONNECTORS_SLF (R78.2)
HALLA: DRV7308EVM_rev1_DRIVER_SLF (J4.13), DRV7308EVM_rev1_POWER_AND_CONNECTORS_SLF (C25.1 J7.4 R29.1)
HALLB: DRV7308EVM_rev1_DRIVER_SLF (R138.1 R139.2), DRV7308EVM_rev1_POWER_AND_CONNECTORS_SLF (C26.1 J7.3 R30.1)
HALLC: DRV7308EVM_rev1_DRIVER_SLF (J3.7), DRV7308EVM_rev1_POWER_AND_CONNECTORS_SLF (C27.1 J7.2 R31.1)
ILIMIT: DRV7308EVM_rev1_DRIVER_SLF (TP36.1 U1.2), DRV7308EVM_rev1_POWER_AND_CONNECTORS_SLF (C35.1 R118.1 R119.2)
ISENA: DRV7308EVM_rev1_DRIVER_SLF (J3.14), DRV7308EVM_rev1_POWER_AND_CONNECTORS_SLF (C47.1 R70.1 R107.2 TP55.1)
ISENB: DRV7308EVM_rev1_DRIVER_SLF (J3.16), DRV7308EVM_rev1_POWER_AND_CONNECTORS_SLF (C48.1 R71.1 R108.2 TP56.1)
ISENC: DRV7308EVM_rev1_DRIVER_SLF (J3.18), DRV7308EVM_rev1_POWER_AND_CONNECTORS_SLF (C49.1 R72.1 R109.2 TP57.1)
OUTA: DRV7308EVM_rev1_DRIVER_SLF (14 pins), DRV7308EVM_rev1_POWER_AND_CONNECTORS_SLF (L2.1)
OUTB: DRV7308EVM_rev1_DRIVER_SLF (11 pins), DRV7308EVM_rev1_POWER_AND_CONNECTORS_SLF (L3.1)
OUTC: DRV7308EVM_rev1_DRIVER_SLF (14 pins), DRV7308EVM_rev1_POWER_AND_CONNECTORS_SLF (L4.1)
SLEW: DRV7308EVM_rev1_DRIVER_SLF (TP24.1 U1.65), DRV7308EVM_rev1_POWER_AND_CONNECTORS_SLF (J1.2 J1.4 J1.6 J1.8)
SNA: DRV7308EVM_rev1_DRIVER_SLF (NT6.2 R11.1), DRV7308EVM_rev1_POWER_AND_CONNECTORS_SLF (R59.1 TP31.1)
SNB: DRV7308EVM_rev1_DRIVER_SLF (NT4.2), DRV7308EVM_rev1_POWER_AND_CONNECTORS_SLF (R52.1 TP14.1)
SNC: DRV7308EVM_rev1_DRIVER_SLF (NT8.2), DRV7308EVM_rev1_POWER_AND_CONNECTORS_SLF (R65.1 TP54.1)
SPA: DRV7308EVM_rev1_DRIVER_SLF (NT5.2 R9.1 TP47.1), DRV7308EVM_rev1_POWER_AND_CONNECTORS_SLF (R61.1)
SPB: DRV7308EVM_rev1_DRIVER_SLF (NT3.2 TP48.1), DRV7308EVM_rev1_POWER_AND_CONNECTORS_SLF (R55.1)
SPC: DRV7308EVM_rev1_DRIVER_SLF (NT7.2 TP49.1), DRV7308EVM_rev1_POWER_AND_CONNECTORS_SLF (R67.1)
VSENA: DRV7308EVM_rev1_DRIVER_SLF (J3.6), DRV7308EVM_rev1_POWER_AND_CONNECTORS_SLF (6 pins)
VSENB: DRV7308EVM_rev1_DRIVER_SLF (J3.8), DRV7308EVM_rev1_POWER_AND_CONNECTORS_SLF (6 pins)
VSENC: DRV7308EVM_rev1_DRIVER_SLF (J3.10), DRV7308EVM_rev1_POWER_AND_CONNECTORS_SLF (6 pins)
VSENVM: DRV7308EVM_rev1_DRIVER_SLF (J3.12), DRV7308EVM_rev1_POWER_AND_CONNECTORS_SLF (6 pins)

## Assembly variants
001: not fitted C6 C12 C12 C16 C17 C24 C35 C36 C36 C37 C37 C40 C40 C41 C41 C43 C43 C44 C44 C46 C46 C50 C59 C60 C61 C62 C63 C64 C67 D13 D14 D15 D16 FID1 FID2 FID3 R34 R36 R49 R50 R51 R78 R107 R108 R109 R123 R124 R126 R127 R136 R137 R140
002: not fitted C35 D13 FID1 FID2 FID3 R2 R13 R32 R33 R34 R48 R51 R78 R107 R108 R109 R123 R124 R126 R127 U1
